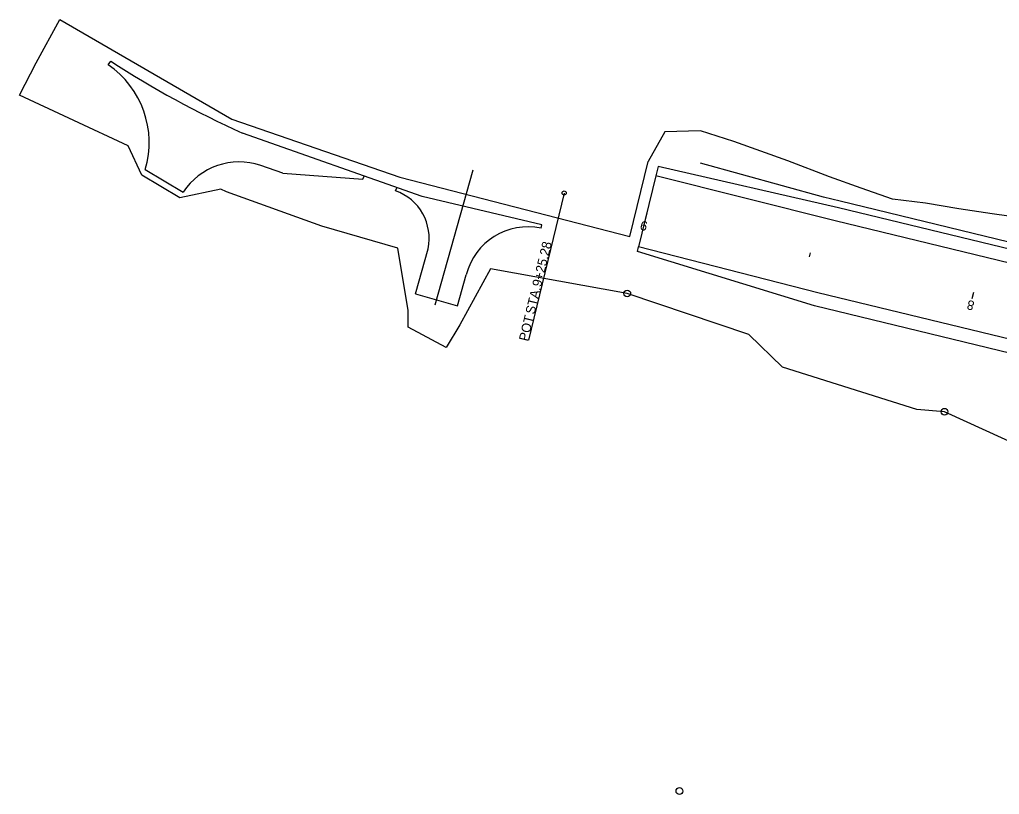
# Model space of a CAD drawing. Extents: x 2479399 to 2480150, y 287222 to 287843.
# Drawn here: x 2479399.5 to 2479690.9, y 287612.4 to 287842.8 of the extents above; entities that cross this region are included whole.
import ezdxf

# ---------------------------------------------------------------- set-up
doc = ezdxf.new("R2010")
doc.units = 0
for name, color, linetype in [('_CIVIL_CONSTRUCTION', 7, 'Continuous'), ('BD_P_Building', 7, 'Continuous'), ('GE_P_Alignment', 7, 'Continuous'), ('GE_P_Alignment_100_Distances', 7, 'Continuous'), ('GE_X_Alignment', 7, 'Continuous'), ('GE_X_Alignment_100_Bearings', 7, 'Continuous'), ('GE_X_Alignment_100_Cardinal_Points', 7, 'Continuous'), ('GE_X_Alignment_100_Curve_Data', 7, 'Continuous'), ('PF_P_Grade_Line', 7, 'Continuous'), ('SC_Scratch10', 7, 'Continuous')]:
    doc.layers.add(name, color=color, linetype=linetype)

msp = doc.modelspace()

# ---------------------------------------------------------------- linework, layer by layer
at = {"layer": '_CIVIL_CONSTRUCTION'}
msp.add_line((2479638.61, 287790.06), (2479601.98, 287800.14), dxfattribs=at)
msp.add_lwpolyline([(2479862.11, 287735.73), (2479643.48, 287788.84), (2479638.61, 287790.06)], dxfattribs=at)
at = {"layer": 'BD_P_Building'}
for centre in [(2479580.2, 287761.4), (2479674.57, 287726.24), (2479595.71, 287613.45)]:
    msp.add_circle(centre, 1, dxfattribs=at)
at = {"layer": 'GE_P_Alignment'}
msp.add_line((2479534.3, 287798.04), (2479522.98, 287757.92), dxfattribs=at)
msp.add_arc((2479506.28, 287777.78), 15, 348.1315, 70.5296, dxfattribs=at)
at = {"layer": 'GE_P_Alignment_100_Distances'}
msp.add_line((2479561.44, 287791.27), (2479550.81, 287747.55), dxfattribs=at)
msp.add_circle((2479561.44, 287791.27), 0.6, dxfattribs=at)
at = {"layer": 'GE_X_Alignment'}
for p, q in [((2479642.05, 287783.01), (2479588.7, 287796.38)), ((2479854.62, 287731.37), (2479642.05, 287783.01)), ((2479636.85, 287761.63), (2479583.57, 287775.3)), ((2479851.06, 287709.6), (2479636.85, 287761.63))]:
    msp.add_line(p, q, dxfattribs=at)
at = {"layer": 'GE_X_Alignment_100_Bearings'}
for p, q in [((2479589.36, 287799.13), (2479588.7, 287796.38)), ((2479642.99, 287786.9), (2479589.36, 287799.13)), ((2479857.2, 287734.86), (2479642.99, 287786.9)), ((2479583.24, 287773.92), (2479583.57, 287775.3)), ((2479635.91, 287757.75), (2479583.24, 287773.92)), ((2479850.12, 287705.71), (2479635.91, 287757.75))]:
    msp.add_line(p, q, dxfattribs=at)
at = {"layer": 'GE_X_Alignment_100_Cardinal_Points'}
msp.add_line((2479588.7, 287796.38), (2479583.55, 287775.22), dxfattribs=at)
at = {"layer": 'GE_X_Alignment_100_Curve_Data'}
for p, q in [((2479591.34, 287809.47), (2479586.42, 287800.64)), ((2479435.84, 287796.57), (2479431.8, 287805.28)), ((2479580.92, 287778.38), (2479586.42, 287800.64)), ((2479447.11, 287789.81), (2479435.84, 287796.57)), ((2479459.3, 287792.41), (2479447.11, 287789.81)), ((2479515.07, 287756.35), (2479511.96, 287774.86)), ((2479539.5, 287768.77), (2479530.45, 287752.04)), ((2479580.2, 287761.4), (2479539.5, 287768.77))]:
    msp.add_line(p, q, dxfattribs=at)
for points in [[(2479431.8, 287805.28), (2479399.47, 287820.41), (2479404.42, 287829.94), (2479411.4, 287842.84), (2479462.57, 287813.2), (2479512.6, 287796.02), (2479580.92, 287778.38)], [(2479698.66, 287783.69), (2479688.68, 287785.12), (2479678.77, 287786.6), (2479668.86, 287788.26), (2479659.04, 287789.47), (2479649.77, 287792.73), (2479640.33, 287796.13), (2479627.97, 287800.85), (2479611.93, 287806.55), (2479602.03, 287809.73), (2479591.34, 287809.47)], [(2479511.96, 287774.86), (2479489.32, 287781.43), (2479461.03, 287791.6), (2479459.3, 287792.41)], [(2479723.7, 287643.63), (2479718.68, 287661.66), (2479720.89, 287705.14), (2479674.57, 287726.24), (2479674.57, 287726.24), (2479674.57, 287726.24), (2479674.57, 287726.24), (2479674.57, 287726.24), (2479666.37, 287726.86), (2479626.33, 287739.49), (2479616.34, 287749.17), (2479616.34, 287749.17), (2479616.34, 287749.17), (2479580.2, 287761.4)], [(2479530.45, 287752.04), (2479526.37, 287745.38), (2479515.01, 287751.35), (2479515.07, 287756.35)]]:
    msp.add_lwpolyline(points, dxfattribs=at)
at = {"layer": 'PF_P_Grade_Line'}
for p, q in [((2479586, 287785.31), (2479585.53, 287783.36)), ((2479634.59, 287773.5), (2479634.31, 287772.34)), ((2479683.18, 287761.7), (2479682.71, 287759.76))]:
    msp.add_line(p, q, dxfattribs=at)
at = {"layer": 'SC_Scratch10'}
for p, q in [((2479425.81, 287829.4), (2479426.56, 287830.51)), ((2479519.17, 287790.19), (2479465.75, 287809.08)), ((2479436.86, 287798.28), (2479448.1, 287791.55)), ((2479477.81, 287797.2), (2479471.18, 287799.45)), ((2479477.81, 287797.2), (2479501.58, 287795.35)), ((2479501.58, 287795.35), (2479501.91, 287796.29)), ((2479511.28, 287791.92), (2479511.62, 287792.86)), ((2479554.83, 287781.78), (2479519.17, 287790.19)), ((2479554.6, 287780.81), (2479554.83, 287781.78)), ((2479517.19, 287761.3), (2479520.96, 287774.69)), ((2479529.7, 287757.77), (2479532.28, 287766.94)), ((2479517.19, 287761.3), (2479529.7, 287757.77))]:
    msp.add_line(p, q, dxfattribs=at)
for centre, radius, start, end in [((2479587.95, 288079.03), 296.32, 237.0006, 245.6445), ((2479410.03, 287806.27), 28, 343.4297, 55.6976), ((2479464.77, 287780.5), 20, 71.3148, 146.4489), ((2479506.28, 287777.78), 15, 348.1315, 70.5296), ((2479550.7, 287762.2), 19.02, 78.1645, 165.5475)]:
    msp.add_arc(centre, radius, start, end, dxfattribs=at)

# ---------------------------------------------------------------- texts
at = {"layer": 'GE_P_Alignment_100_Distances'}
for s, p in [('9+25.28', (2479554.57, 287763.2)), (' STA. ', (2479552.34, 287754.02)), ('POT', (2479550.64, 287747.02))]:
    msp.add_text(s, height=2.8, rotation=76.3463, dxfattribs=at).set_placement(p)
at = {"layer": 'PF_P_Grade_Line'}
for s, p in [('9', (2479586.47, 287782.62)), ('8', (2479683.66, 287759.01))]:
    msp.add_text(s, height=2.8, rotation=166.3463, dxfattribs=at).set_placement(p)

doc.saveas('drawing.dxf')
